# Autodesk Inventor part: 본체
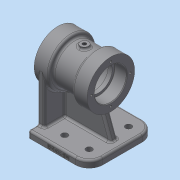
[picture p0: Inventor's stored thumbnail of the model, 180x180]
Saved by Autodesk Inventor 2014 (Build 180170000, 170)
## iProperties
Created: 2020-06
Part Number: 본체
Material: Generic
Document SubType Name: Modeling
Designer: kh
Density: 1 g/cm^3
Appearance: Default
Mass: 254.581 g
Surface Area: 616.877 cm^2
Volume: 254.581 cm^3
Author: kh
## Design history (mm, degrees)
sketch "Sketch1"
  geometry: L1 (-45, -49)-(45, -49); L2 (45, -49)-(45, 49); L3 (45, 49)-(-45, 49); L4 (-45, 49)-(-45, -49); L5 (-45, -49)-(45, 49); L6 (45, -49)-(-45, 49); 1 further point
  constraints: 12 end point, 2 midpoint, 2 parallel, 1 horizontal, 1 perpendicular
  dimensions: "d0" = 90 distance of L2.end L3.end; "d1" = 98 distance of L1.end L2.end
extrude "Extrusion1" new body sketch "Sketch1" distance "d2" = 10; taper "d3" = 0 deg
sketch "Sketch2"
  geometry: L1 (115.272, 80)-(-57.439, 80); L2 (50, 80)-(50, 115); L3 (50, 115)-(28, 115); L4 (28, 115)-(28, 109); L5 (28, 109)-(-6, 109); L6 (-6, 109)-(-6, 115); L7 (-6, 115)-(-28, 115); L8 (-28, 115)-(-28, 80); L9 (45, 0)-(45, 10) reference; L10 (50, 80)-(-28, 80); L11 (45, 0)-(-45, 0) reference; 1 further point
  constraints: 18 end point, 4 parallel, 3 perpendicular, 2 point on line, 1 collinear, 1 horizontal
  dimensions: "d4" = 5 distance between parallel lines of L9 L2; "d5" = 22 distance of L2.end L3.end; "d6" = 22 distance of L6.end L7.end; "d7" = 78 distance between parallel lines of L8 L2; "d8" = 70 diameter of L3 L1; "d9" = 58 diameter of L5 L1; "d10" = 70 diameter of L7 L1; "d94" = 80 distance between parallel lines of L11 L1
revolve "Revolution1" sketch "Sketch2" stored, may be unused: angle "d11" = 90 deg
workplane "Work Plane2"
  workplane "Work Plane1"
sketch "Sketch3"
  geometry: L1 (-39, 35)-(-39, -35) reference; C1 r 6 at (0, 0); 1 further point
  constraints: 1 centre point, 1 horizontal alignment
  dimensions: "d13" = 12 diameter of C1; "d14" = 39 distance from line of C1.centre L1
extrude "Extrusion2" join sketch "Sketch3" stored distance "d15" = 10; taper "d16" = 0 deg
sketch "Sketch4"
  geometry: L1 (-45, 49)-(-45, -49) reference; L2 (-45, 35)-(-35, 35); L3 (-35, 35)-(-35, -35); L4 (-35, -35)-(-45, -35); 2 further points
  constraints: 6 end point, 3 perpendicular, 2 point on line, 1 horizontal alignment, 1 midpoint
  dimensions: "d17" = 70 distance between parallel lines of L4 L2; "d18" = 10 distance of L2.start L2.end
extrude "Extrusion3" join sketch "Sketch4" stored distance "d19" = 10; taper "d20" = 0 deg
sketch "Sketch5"
  geometry: L1 (-28, 45)-(-28, 115) reference; L2 (-6, 45)-(-6, 115) reference; L3 (-45, 0)-(45, 0) reference; L4 (45, 0)-(45, 10) reference; L5 (-45, 10)-(45, 10) reference; L6 (-45, 0)-(-45, 10) reference; L7 (-12.102, 67.418)-(-33, 10); L8 (-12.102, 67.418)-(41.961, 67.418); L9 (41.961, 67.418)-(41.961, 10); L10 (41.961, 10)-(-33, 10); 1 further point
  constraints: 8 end point, 2 perpendicular, 2 point on line, 1 collinear
  dimensions: "d21" = 70 deg angle of L5 L7; "d22" = 12 distance from line of L6 L7.end
extrude "Extrusion4" join sketch "Sketch5" stored distance "d23" = 10; taper "d24" = 0 deg
sketch "Sketch6"
  geometry: L1 (50, 45)-(50, 115) reference; L2 (50, 103.5)-(32, 103.5); L3 (32, 103.5)-(32, 100); L4 (32, 100)-(26, 100); L5 (26, 100)-(26, 103); L6 (26, 103)-(-4, 103); L7 (-4, 103)-(-4, 100); L8 (-4, 100)-(-10, 100); L9 (-10, 100)-(-10, 103.5); L10 (-10, 103.5)-(-28, 103.5); L11 (-28, 45)-(-28, 115) reference; L12 (50, 80)-(-58.784, 80); L13 (50, 103.5)-(50, 80); L14 (50, 80)-(-28, 80); L15 (-28, 80)-(-28, 103.5); 1 further point
  constraints: 26 end point, 6 parallel, 3 perpendicular, 3 point on line, 2 collinear, 2 midpoint
  dimensions: "d34" = 18 distance of L2.start L2.end; "d35" = 6 distance of L3.end L4.end; "d36" = 30 distance of L5.end L6.end; "d37" = 18 distance of L9.end L10.end; "d39" = 47 diameter of L2 L12; "d40" = 40 diameter of L4 L12; "d41" = 46 diameter of L6 L12; "d42" = 40 diameter of L8 L12; "d43" = 47 diameter of L10 L12
revolve "Revolution2" sketch "Sketch6" stored, may be unused: angle "d44" = 90 deg
sketch "Sketch7"
  geometry: C1 r 23.5 at (0, 0) reference; 2 further points
  constraints: 1 horizontal alignment
  dimensions: "d45" = 28.5 distance of C1.centre point (-28.5, 0)
hole "Hole1" sketch "Sketch7" at (-28.5, 0) diameter "d46" = 3.242; stored, may be unused: countersink angle "d50" = 90 deg, drill point angle "d52" = 118 deg; dims "d47" = 10, "d48" = 4, "d49" = 2, "d51" = 12
pattern_circular "Circular Pattern1" dims angle "d54" = 360 deg
workplane "Work Plane3"
mirror "Mirror1"
hole "Hole2" diameter "d58" = 5.188; stored, may be unused: countersink angle "d62" = 90 deg, drill point angle "d64" = 118 deg; dims "d56" = 10, "d57" = 10, "d59" = 10, "d60" = 4, "d61" = 2, "d63" = 12
sketch "Sketch8"
  geometry: L1 (-45, 49)-(-45, 35) reference; 2 further points
  dimensions: "d65" = 70 distance from line of point (25, 29) L1; "d66" = 29 vertical distance of point (0, 0) point (25, 29)
hole "Hole3" sketch "Sketch8" at (25, 29) diameter "d67" = 9; stored, may be unused: countersink angle "d71" = 90 deg, drill point angle "d73" = 0 deg; dims "d68" = 10, "d69" = 4, "d70" = 2, "d72" = 12
pattern_linear "Rectangular Pattern1" dims "d76" = 58, "d79" = 36
chamfer "Chamfer1" distance "d80" = 1; stored, may be unused: second distance "d81" = 2, angle "d82" = 45 deg
fillet "Fillet1" dims "d83" = 20
fillet "Fillet3" dims "d85" = 3
fillet "Fillet4" dims "d86" = 3
fillet "Fillet5" dims "d87" = 3
fillet "Fillet6" dims "d88" = 3
sketch "Sketch9"
  geometry: L1 (0, 0)-(67, 0) reference; L2 (-3, 7)-(-3, 0) reference; 2 further points
  constraints: 1 other
  dimensions: "d90" = 45 distance from line of point (42, 4) L2; "d91" = 4 distance from line of L1 point (42, 4)
emboss "Emboss1" sketch "Sketch9" dims "d0" = 90, "d1" = 98, "d92" = 0.5, "d93" = 0
fillet "Fillet8" dims "d95" = 3
fillet "Fillet9" dims "d96" = 0.3
body "Solid1"
node "Projected Loop1"
node "Projected Loop2"
other parameters: "d12" = 3
